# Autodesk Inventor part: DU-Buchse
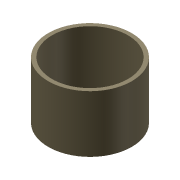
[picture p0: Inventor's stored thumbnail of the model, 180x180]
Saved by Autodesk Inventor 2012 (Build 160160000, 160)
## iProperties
Company: CAD-Verlag
Created: 2004-09
Part Number: DU-Buchse
Document SubType Name: Modeling
Designer: Greiling
Manufacturer: Standard
Standards Organization: Custom
Density: 1 g/cm^3
Checked By: Jürgen Kronas
Stock Number: 10-10015
Material: Standard
Author: Juergen Kronas
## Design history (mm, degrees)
sketch "Skizze1"
  geometry: L1 (35.124, 40)-(47.124, 28) reference; L2 (-42.876, 40)-(35.124, 40) reference; L3 (-42.876, -40)-(-42.876, 40) reference; L4 (35.124, -40)-(-42.876, -40) reference; L5 (47.124, -28)-(35.124, -40) reference; L6 (47.124, 28)-(47.124, -28) reference; C1 r 22 at (-6.876, 0) reference; C2 r 20 at (-6.876, 0)
  constraints: 1 centre point, 1 coincident
  dimensions: "d0" = 40 diameter of C2
extrude "Extrusion1" new body sketch "Skizze1" distance "d1" = 30; taper "d2" = 0 deg
node "Volumenkörper1"
node "Volumenkörpern"
node "Oberflächenkörpern"
node "Referenz1"
